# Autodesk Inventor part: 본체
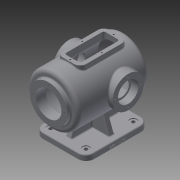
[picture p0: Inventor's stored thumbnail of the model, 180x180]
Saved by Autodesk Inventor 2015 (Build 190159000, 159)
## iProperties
Created: 2021-11
Part Number: 본체
Material: 일반
Document SubType Name: Modeling
Designer: G01
Density: 1 g/cm^3
Appearance: 기본값
Author: G01
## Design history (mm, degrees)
sketch "스케치1"
  geometry: L1 (-65, -80)-(65, -80); L2 (65, -80)-(65, 80); L3 (65, 80)-(-65, 80); L4 (-65, 80)-(-65, -80); L5 (-65, -80)-(65, 80); L6 (65, -80)-(-65, 80); 1 further point
  constraints: 12 end point, 2 midpoint, 2 parallel, 1 horizontal, 1 perpendicular
  dimensions: "d0" = 130 distance of L1.start L1.end; "d1" = 160 distance of L3.end L1.start
extrude "돌출1" new body sketch "스케치1" distance "d2" = 14; taper "d3" = 0 deg
fillet "모깎기1" dims "d4" = 20
fillet "모깎기2" dims "d5" = 3
sketch "스케치2"
  geometry: A1 r 17 centre (45, -60) between (45, -77) and (62, -60) reference; A2 r 17 centre (45, 60) between (62, 60) and (45, 77) reference; A3 r 17 centre (-45, 60) between (-45, 77) and (-62, 60) reference; A4 r 17 centre (-45, -60) between (-62, -60) and (-45, -77) reference; 1 further point
hole "구멍1" sketch "스케치2" at (-45, -60), (45, -60), (45, 60), (-45, 60) diameter "d6" = 9; stored, may be unused: countersink angle "d10" = 90 deg, drill point angle "d12" = 118 deg; dims "d7" = 6, "d8" = 18, "d9" = 2, "d11" = 8
sketch "스케치3"
  geometry: L1 (-65, 60)-(-65, -60) reference; L2 (-45, -80)-(45, -80) reference; L3 (45, 80)-(-45, 80) reference; L4 (65, -60)-(65, 60) reference; L5 (-7, -60)-(7, -60); L6 (7, -60)-(7, 60); L7 (7, 60)-(-7, 60); L8 (-7, 60)-(-7, -60); L9 (-7, -60)-(7, 60); L10 (7, -60)-(-7, 60); L11 (-50, -7)-(50, -7); L12 (50, -7)-(50, 7); L13 (50, 7)-(-50, 7); L14 (-50, 7)-(-50, -7); L15 (-50, -7)-(50, 7); L16 (50, -7)-(-50, 7); 1 further point
  constraints: 24 end point, 4 midpoint, 4 parallel, 2 horizontal, 2 perpendicular
  dimensions: "d13" = 14 distance of L5.start L5.end; "d14" = 14 distance of L13.end L11.start; "d15" = 100 distance of L12.end L13.end; "d16" = 120 distance of L5.end L6.end
extrude "돌출2" join sketch "스케치3" distance "d17" = 100; taper "d18" = 0 deg
feature "면 기울기1" dims angle "d19" = 20 deg
feature "면 기울기2" dims angle "d20" = 20 deg
feature "면 기울기3" dims angle "d21" = 20 deg
feature "면 기울기4" dims angle "d22" = 20 deg
fillet "모깎기7" dims "d70" = 3
fillet "모깎기8" dims "d71" = 3
sketch "스케치4"
  geometry: L1 (80, 11)-(80, 0) reference; L2 (80, 0)-(-80, 0) reference; L3 (-80, 0)-(-80, 11) reference; L4 (-77, 14)-(-62.101, 14) reference; L5 (-59.282, 15.974)-(-23.603, 114) reference; L6 (-23.603, 114)-(23.603, 114) reference; L7 (23.603, 114)-(59.282, 15.974) reference; L8 (62.101, 14)-(77, 14) reference; L9 (100, 114)-(-110, 114); L10 (-110, 114)-(-110, 161.5); L11 (-110, 161.5)-(-100, 161.5); L12 (-100, 161.5)-(-100, 179); L13 (-100, 179)-(75.993, 179); A1 r 3 centre (77, 11) between (80, 11) and (77, 14) reference; A2 r 3 centre (-77, 11) between (-77, 14) and (-80, 11) reference; A3 r 100 centre (0, 114) between (100, 114) and (75.993, 179); A4 r 3 centre (-62.101, 17) between (-62.101, 14) and (-59.282, 15.974) reference; A5 r 3 centre (62.101, 17) between (59.282, 15.974) and (62.101, 14) reference; 3 further points
  constraints: 10 end point, 2 horizontal, 2 midpoint, 2 perpendicular, 2 point on circle, 1 centre point, 1 coincident, 1 point on line, 1 vertical
  dimensions: "d24" = 210 distance of L9.start L9.end; "d25" = 47.5 distance of L9.end L10.end; "d26" = 10 distance of L10.end L11.end; "d28" = 110 distance from line of point (0, 114) L10; "d29" = 65 distance between parallel lines of L9 L13; "d30" = 100 radius of A3
revolve "회전1" sketch "스케치4" stored, may be unused: angle "d31" = 90 deg
sketch "스케치5"
  geometry: L1 (60, 0)-(-60, 0) reference; L2 (-110, 66.5)-(-110, 161.5) reference; L3 (-100, 66.5)-(-100, 161.5) reference; L4 (-110, 114)-(-110, 146.5); L5 (-85, 146.5)-(-85, 169); L6 (-110, 146.5)-(-85, 146.5); L7 (-85, 169)-(71.239, 169); L8 (-110, 114)-(90, 114); L9 (-100, 179)-(75.993, 179) reference; L10 (-110, 161.5)-(-100, 161.5) reference; A1 r 100 centre (0, 114) between (75.993, 49) and (75.993, 179) reference; A2 r 90 centre (0, 114) between (90, 114) and (71.239, 169); 1 further point
  constraints: 10 end point, 3 horizontal, 2 point on circle, 1 centre point, 1 midpoint, 1 point on line, 1 vertical
  dimensions: "d32" = 10 radial gap between concentric circles of A1 A2; "d33" = 25 distance between parallel lines of L5 L2; "d34" = 55 distance between parallel lines of L8 L7; "d35" = 32.5 distance between parallel lines of L8 L6; "d36" = 114 distance between parallel lines of L1 L8
revolve "회전2" sketch "스케치5" stored, may be unused: angle "d37" = 90 deg
fillet "모깎기3" dims "d38" = 3
node "작업 평면1"
sketch "스케치6"
  geometry: L1 (30, -60)-(-30, -60); L2 (-30, -60)-(-30, 60); L3 (-30, 60)-(30, 60); L4 (30, 60)-(30, -60); L5 (30, -60)-(-30, 60); L6 (-30, -60)-(30, 60); L7 (47.5, -110)-(-47.5, -110) reference; 3 further points
  constraints: 12 end point, 3 midpoint, 2 parallel, 1 coincident, 1 horizontal, 1 perpendicular
  dimensions: "d40" = 50 distance between parallel lines of L1 L7; "d41" = 60 distance of L2.end L3.end; "d42" = 120 distance of L3.end L1.start
extrude "돌출3" join sketch "스케치6" stored distance "d43" = 10; taper "d44" = 0 deg
fillet "모깎기4" dims "d45" = 15
fillet "모깎기5" dims "d46" = 3
sketch "스케치7"
  geometry: L1 (-15, -60)-(15, -60) reference; L2 (30, -45)-(30, 45) reference; L3 (15, 60)-(-15, 60) reference; L4 (-30, 45)-(-30, -45) reference; L5 (-15, -50)-(15, -50); L6 (20, -45)-(20, 45); L7 (15, 50)-(-15, 50); L8 (-20, 45)-(-20, -45); A1 r 15 centre (-15, -45) between (-30, -45) and (-15, -60) reference; A2 r 15 centre (15, -45) between (15, -60) and (30, -45) reference; A3 r 15 centre (15, 45) between (30, 45) and (15, 60) reference; A4 r 15 centre (-15, 45) between (-15, 60) and (-30, 45) reference; A5 r 5 centre (-15, -45) between (-20, -45) and (-15, -50); A6 r 5 centre (15, -45) between (15, -50) and (20, -45); A7 r 5 centre (15, 45) between (20, 45) and (15, 50); A8 r 5 centre (-15, 45) between (-15, 50) and (-20, 45); 1 further point
  constraints: 8 end point, 8 point on circle, 4 centre point, 7 other
  dimensions: "d47" = 10 distance between parallel lines of L8 L4
extrude "돌출4" cut sketch "스케치7" distance "d48" = 50; taper "d49" = 0 deg
sketch "스케치8"
  geometry: L1 (-15, -60)-(15, -60) reference; L2 (30, -45)-(30, 45) reference; L3 (15, 60)-(-15, 60) reference; L4 (-30, 45)-(-30, -45) reference; L5 (-15, -55)-(15, -55); L6 (25, -45)-(25, 45); L7 (15, 55)-(-15, 55); L8 (-25, 45)-(-25, -45); A1 r 15 centre (-15, -45) between (-30, -45) and (-15, -60) reference; A2 r 15 centre (15, -45) between (15, -60) and (30, -45) reference; A3 r 15 centre (15, 45) between (30, 45) and (15, 60) reference; A4 r 15 centre (-15, 45) between (-15, 60) and (-30, 45) reference; A5 r 10 centre (-15, -45) between (-25, -45) and (-15, -55); A6 r 10 centre (15, -45) between (15, -55) and (25, -45); A7 r 10 centre (15, 45) between (25, 45) and (15, 55); A8 r 10 centre (-15, 45) between (-15, 55) and (-25, 45); 5 further points
  constraints: 8 end point, 8 point on circle, 4 centre point, 4 midpoint, 7 other
  dimensions: "d50" = 5 distance between parallel lines of L8 L4
hole "구멍2" sketch "스케치8" at (0, -55), (0, 55), (-25, 0), (25, 0) diameter "d51" = 3.242; stored, may be unused: countersink angle "d55" = 90 deg, drill point angle "d57" = 118 deg; dims "d52" = 9, "d53" = 4, "d54" = 2, "d56" = 11
fillet "모깎기6" dims "d58" = 3
sketch "스케치9"
  geometry: C1 r 32.5 at (0, 0) reference; 2 further points
  constraints: 1 vertical alignment
  dimensions: "d59" = 40 distance of C1.centre point (0, 40)
hole "구멍3" sketch "스케치9" at (0, 40) diameter "d60" = 3.242; stored, may be unused: countersink angle "d64" = 90 deg, drill point angle "d66" = 118 deg; dims "d61" = 11, "d62" = 4, "d63" = 2, "d65" = 13
sketch "스케치10"
  geometry: L1 (-60, 182)-(-60, 184) reference; L2 (-60, 184)-(-56.621, 184) reference; L3 (-56.621, 184)-(-56.621, 173) reference; L4 (-56.621, 173)-(-55, 172.026) reference; L5 (-55, 172.026)-(-53.379, 173) reference; L6 (-53.379, 173)-(-53.379, 184) reference; L7 (-53.379, 184)-(-50, 184) reference; L8 (-50, 184)-(-50, 172) reference; L9 (-53, 169)-(-82, 169) reference; L10 (-85, 166)-(-85, 146.5) reference; L11 (-85, 146.5)-(-110, 146.5) reference; L12 (-110, 146.5)-(-110, 152.379) reference; L13 (-110, 152.379)-(-97, 152.379) reference; L14 (-97, 152.379)-(-96.026, 154) reference; L15 (-96.026, 154)-(-97, 155.621) reference; L16 (-97, 155.621)-(-110, 155.621) reference; L17 (-110, 155.621)-(-110, 161.5) reference; L18 (-110, 161.5)-(-100, 161.5) reference; L19 (-100, 161.5)-(-100, 179) reference; L20 (-100, 179)-(-63, 179) reference; L21 (80, 0)-(-80, 0) reference; L22 (-80, 0)-(-80, 11) reference; L23 (-77, 14)-(-62.101, 14) reference; L24 (-59.282, 15.974)-(-47.261, 49) reference; L25 (-47.261, 49)-(-100, 49) reference; L26 (-100, 49)-(-100, 66.5) reference; L27 (-100, 66.5)-(-110, 66.5) reference; L28 (-110, 66.5)-(-110, 72.379) reference; L29 (-110, 72.379)-(-97, 72.379) reference; L30 (-97, 72.379)-(-96.026, 74) reference; L31 (-96.026, 74)-(-97, 75.621) reference; L32 (-97, 75.621)-(-110, 75.621) reference; L33 (-110, 75.621)-(-110, 81.5) reference; L34 (-110, 81.5)-(-85, 81.5) reference; L35 (-85, 81.5)-(-85, 62) reference; L36 (-82, 59)-(69.75, 59) reference; L37 (69.75, 169)-(53, 169) reference; L38 (50, 172)-(50, 184) reference; L39 (50, 184)-(53.379, 184) reference; L40 (53.379, 184)-(53.379, 173) reference; L41 (53.379, 173)-(55, 172.026) reference; L42 (55, 172.026)-(56.621, 173) reference; L43 (56.621, 173)-(56.621, 184) reference; L44 (56.621, 184)-(60, 184) reference; L45 (60, 184)-(60, 182) reference; L46 (63, 179)-(75.993, 179) reference; L47 (75.993, 49)-(47.261, 49) reference; L48 (47.261, 49)-(59.282, 15.974) reference; L49 (62.101, 14)-(77, 14) reference; L50 (80, 11)-(80, 0) reference; C1 r 21 at (17, 114); A1 r 3 centre (-63, 182) between (-63, 179) and (-60, 182) reference; A2 r 3 centre (-53, 172) between (-53, 169) and (-50, 172) reference; A3 r 3 centre (-82, 166) between (-82, 169) and (-85, 166) reference; A4 r 3 centre (-77, 11) between (-77, 14) and (-80, 11) reference; A5 r 3 centre (-62.101, 17) between (-62.101, 14) and (-59.282, 15.974) reference; A6 r 3 centre (-82, 62) between (-85, 62) and (-82, 59) reference; A7 r 3 centre (69.75, 62) between (69.75, 59) and (72.155, 60.207) reference; A8 r 90 centre (0, 114) between (72.155, 60.207) and (72.155, 167.793) reference; A9 r 3 centre (69.75, 166) between (72.155, 167.793) and (69.75, 169) reference; A10 r 3 centre (53, 172) between (50, 172) and (53, 169) reference; A11 r 3 centre (63, 182) between (60, 182) and (63, 179) reference; A12 r 100 centre (0, 114) between (75.993, 49) and (75.993, 179) reference; A13 r 3 centre (62.101, 17) between (59.282, 15.974) and (62.101, 14) reference; A14 r 3 centre (77, 11) between (80, 11) and (77, 14) reference; 1 further point
  constraints: 1 centre point
  dimensions: "d72" = 42 diameter of C1; "d73" = 114 distance from line of L21 C1.centre; "d74" = 127 horizontal distance of C1.centre L17.end
  node "절단 모서리 투영2"
node "작업 평면2"
sketch "스케치11"
  geometry: L1 (-60, 0)-(60, 0) reference; L2 (-110, 66.5)-(-110, 161.5) reference; C1 r 40 at (17, 114); 1 further point
  constraints: 1 centre point
  dimensions: "d76" = 80 diameter of C1; "d77" = 127 distance from line of C1.centre L2; "d78" = 114 distance from line of L1 C1.centre
extrude "돌출5" join sketch "스케치11" stored distance "d79" = 150; taper "d80" = 0 deg
fillet "모깎기9" dims "d81" = 3
sketch "스케치12"
  geometry: C1 r 40 at (0, 0) reference; 1 further point
hole "구멍4" sketch "스케치12" at (0, 0) diameter "d82" = 42; stored, may be unused: countersink angle "d86" = 90 deg, drill point angle "d88" = 118 deg; dims "d83" = 42, "d84" = 52, "d85" = 18, "d87" = 13
sketch "스케치13"
  geometry: C1 r 21 at (0, 0) reference; C2 r 40 at (0, 0) reference; C3 r 26 at (0, 0); 1 further point
  constraints: 1 centre point, 1 coincident
  dimensions: "d89" = 52 diameter of C3
extrude "돌출6" cut sketch "스케치13" distance "d90" = 18; taper "d91" = 0 deg
fillet "모깎기10" dims "d92" = 0.3
sketch "스케치14"
  geometry: C1 r 26 at (0, 0) reference; 2 further points
  constraints: 1 horizontal alignment
  dimensions: "d93" = 32.5 distance of C1.centre point (-32.5, 0)
hole "구멍5" sketch "스케치14" at (-32.5, 0) diameter "d94" = 3.242; stored, may be unused: countersink angle "d98" = 90 deg, drill point angle "d100" = 118 deg; dims "d95" = 11, "d96" = 52, "d97" = 18, "d99" = 13
fillet "모깎기11" dims "d104" = 10
fillet "모깎기12" dims "d105" = 3
fillet "모깎기13" dims "d106" = 10
sketch "스케치15"
  geometry: L1 (0, 0)-(0, 120) reference; 4 further points
  constraints: 2 horizontal alignment, 2 midpoint, 1 other
  dimensions: "d107" = 5 distance from line of L1 point (-5, 60)
feature "엠보싱1" sketch "스케치15" dims "d4" = 20, "d108" = 0.5, "d109" = 0
node "솔리드1"
pattern_circular "원형 패턴1" dims angle "d68" = 360 deg
mirror "대칭1"
pattern_circular "원형 패턴2" dims angle "d102" = 360 deg
mirror "대칭2"
node "투영된 루프1"
node "절단 모서리 투영1"
other parameters: "d39" = -184, "d75" = 75
